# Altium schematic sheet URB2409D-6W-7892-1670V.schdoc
size 277 x 190 mm; Device: default297x210; Symbol: default297x210; Name: default297x210; Date: 2025.06.10; Rev: V1.1; Size: "A4"; Id: /; File: URB2409D-6W-7892-1670V; Sheet: /; @Page No: 1; @Page Count: 1; @Schematic Name: URB2409D-6W-7892-1670V; @Project Name: 无光耦反激隔离电源-URB2409D-6W-7892-1670V; @Board Name: URB2409D-6W-7892-1670V; @Update Date: 2025-06-10; @Create Time: 15:27:42; @Update Time: 11:03:09; @Page Name: URB2409D-6W-7892-1670V; @Create Date: 2025-06-09
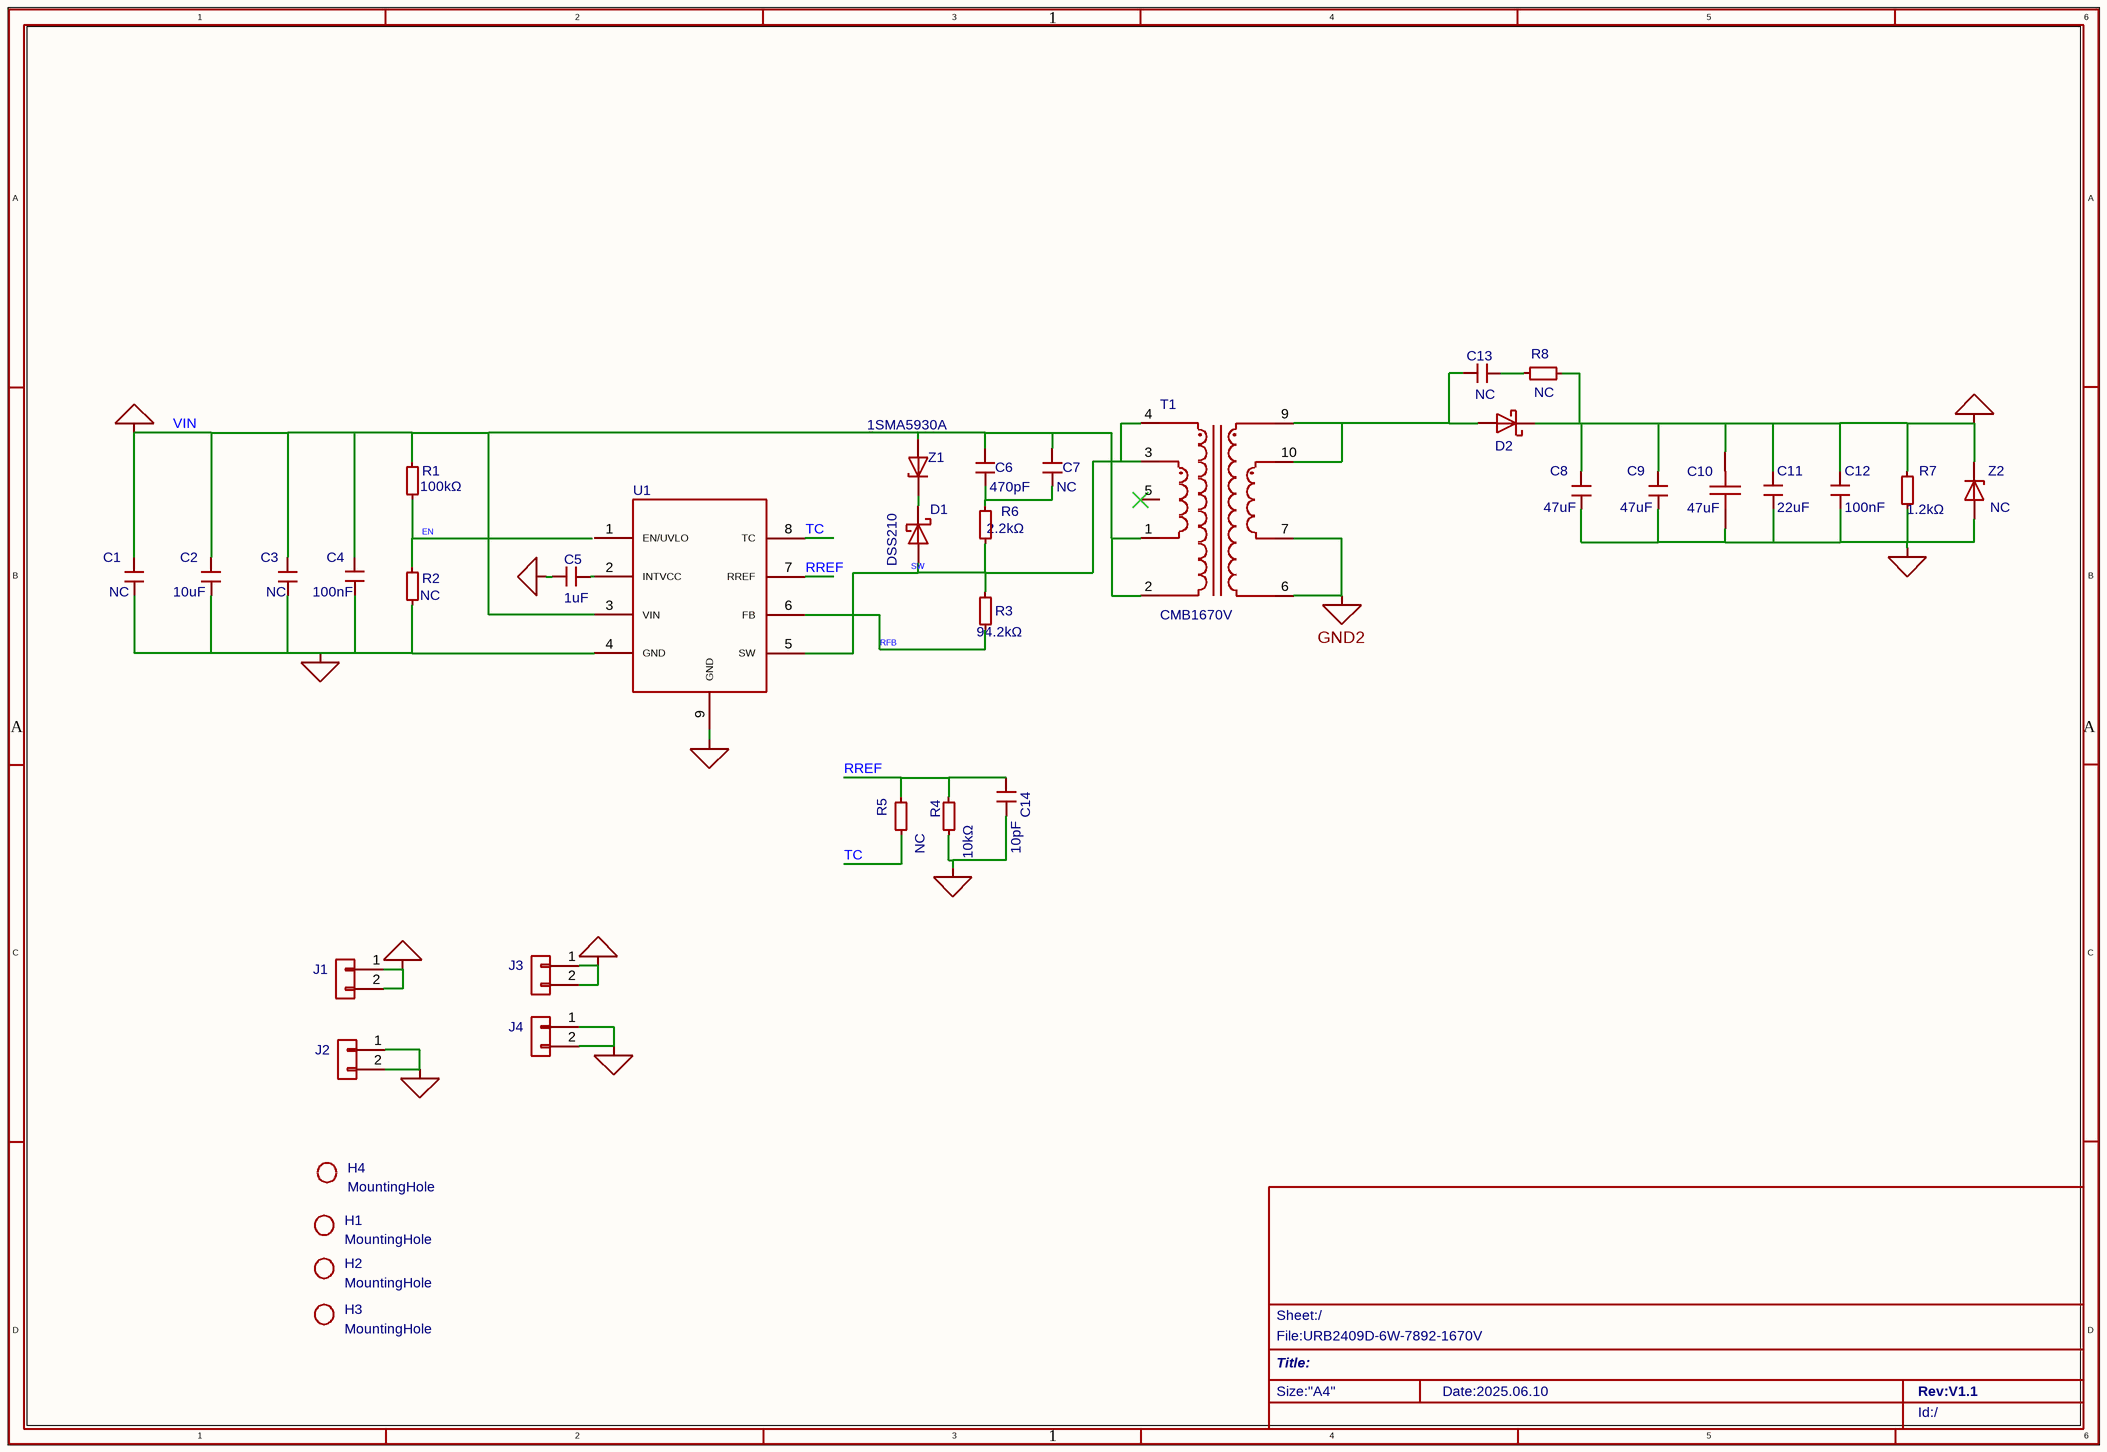
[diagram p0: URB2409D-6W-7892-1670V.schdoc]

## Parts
C1  NC  [C1206]
C2  10uF  [C1206]
C3  NC  [C0805]
C4  100nF  [C0603]
C5  1uF  [C0603]
C6  470pF  [C0603]
C7  NC  [C0603]
C8  47uF  [C1206]
C9  47uF  [C1206]
C10  47uF  [C1206]
C11  22uF  [C0603]
C12  100nF  [C0603]
C13  NC  [C0603]
C14  10pF  [C0603]
D1  DSS210  [SOD-123_L2.8-W1.8-LS3.7-FD]
D2  SSL510B  [SMB_L4.6-W3.5-LS5.3-RD]  (value not drawn)
H1  value MountingHole  [MountingHole:MountingHole_3.2mm_M3_DIN965]  (hidden comment: Mechanical_MountingHole)
H2  value MountingHole  [MountingHole:MountingHole_3.2mm_M3_DIN965]  (hidden comment: Mechanical_MountingHole)
H3  value MountingHole  [MountingHole:MountingHole_3.2mm_M3_DIN965]  (hidden comment: Mechanical_MountingHole)
H4  value MountingHole  [MountingHole:MountingHole_3.2mm_M3_DIN965]  (hidden comment: Mechanical_MountingHole)
J1  Connector_Generic_Conn_01x02  [Connector_PinHeader_2.54mm:PinHeader_1x02_P2.54mm_Vertical]  (value not drawn)
J2  Connector_Generic_Conn_01x02  [Connector_PinHeader_2.54mm:PinHeader_1x02_P2.54mm_Vertical]  (value not drawn)
J3  Connector_Generic_Conn_01x02  [Connector_PinHeader_2.54mm:PinHeader_1x02_P2.54mm_Vertical]  (value not drawn)
J4  Connector_Generic_Conn_01x02  [Connector_PinHeader_2.54mm:PinHeader_1x02_P2.54mm_Vertical]  (value not drawn)
R1  100kΩ  [R0603]
R2  NC  [R0603]
R3  94.2kΩ  [R0603]
R4  10kΩ  [R0603]
R5  value NC  [R0603]  (hidden comment: Device_R_Small)
R6  2.2kΩ  [R0603]
R7  1.2kΩ  [R0603]
R8  value NC  [R0603]  (hidden comment: Device_R_Small)
T1  CMB1670V  [XFMR-SMD_CMB1670V]
U1  (no value)  [ESOP-8_L4.9-W3.9-P1.27-LS6.0-TL-EP3.3]
Z1  1SMA5930A  [SMA_L4.3-W2.6-LS5.2-RD]
Z2  value NC  [DIODE-SMA]  (hidden comment: Diode_BZV55C75)

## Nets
GND1: C1.2 C2.2 C3.2 C4.1 C5.1 C14.1 J2.1(Pin_1) J2.2(Pin_2) R2.2 R4.2 U1.4(GND) U1.9(GND)
GND2: C8.2 C9.2 C10.1 C11.1 C12.1 J4.1(Pin_1) J4.2(Pin_2) R7.1 T1.6 T1.7 Z2.2(A)
VIN: C1.1 C2.1 C3.1 C4.2 C6.1 C7.1 J1.1(Pin_1) J1.2(Pin_2) R1.1 T1.1 T1.2 U1.3(VIN) Z1.2(A)
VOUT: C8.1 C9.1 C10.2 C11.2 C12.2 D2.1(K) J3.1(Pin_1) J3.2(Pin_2) R7.2 R8.1 Z2.1(K)
EN: R1.2 R2.1
RFB: R3.1 U1.6(FB)
RREF: C14.2 R4.1 R5.2 U1.7(RREF)
SW: D1.2(A) R3.2 R6.1 T1.3 T1.4 U1.5(SW)
TC: R5.1 U1.8(TC)
NetC5_2: C5.2 U1.2(INTVCC)
NetC6_2: C6.2 C7.2 R6.2
NetC13_1: C13.1 R8.2
NetC13_2: C13.2 D2.2(A) T1.9 T1.10
NetD1_1: D1.1(K) Z1.1(K)

Not connected (* = marked no-connect by the designer): T1 5*; U1 1(EN/UVLO)

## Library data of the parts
C1 = CC1206KKX5R9BB106: 容值:10uF;精度:±10%;额定电压:50V;材质(温度系数):X5R;; Manufacturer: YAGEO(国巨); Add into BOM: no; Symbol: MY_C; ConvertToPcb: yes; ModelId: e4be705b945545a48e666415e3682bd8; ModelName: C1206_L3.2-W1.6-H1.3; ModelTransform: 125.984,62.992,0,0,0,0,0,0,0; Tolerance: ±10%; Voltage Rated: 50V; Temperature Coefficient: X5R
C2 = CC1206KKX7R8BB106: 容值:10uF;精度:±10%;额定电压:25V;材质(温度系数):X7R;; Manufacturer: YAGEO(国巨); Symbol: MY_C; AddInBom: yes; ModelId: e4be705b945545a48e666415e3682bd8; ModelName: C1206_L3.2-W1.6-H1.3; ModelTransform: 125.984,62.992,0,0,0,0,0,0,0; Tolerance: ±10%; Voltage Rated: 25V; Temperature Coefficient: X7R
C3 = CGA0805X5R476M100MT: 容值:47uF;精度:±20%;额定电压:10V;温度系数:X5R;; Manufacturer: HRE(芯声); Add into BOM: no; Symbol: MY_C; ConvertToPcb: yes; ModelId: 1ba041120af144c991958decab20d241; ModelName: C0805_L2.0-W1.3-H1.3; ModelTransform: 78.74,51.181,0,0,0,0,0,0.0005,0; Tolerance: ±20%; Voltage Rating: 10V; Temperature Coefficient: X5R
C4 C12 = CC0603KRX7R9BB104: 容值:100nF;精度:±10%;额定电压:50V;材质(温度系数):X7R;; Manufacturer: YAGEO(国巨); Symbol: MY_C; AddInBom: yes; ModelId: ac125912035d415993ca9572d50418b1; ModelName: C0603_L1.6-W0.8-H0.8; ModelTransform: 62.992,31.496,0,0,0,0,0,0,0; Tolerance: ±10%; Voltage Rated: 50V; Temperature Coefficient: X7R
C5 = CC0603KRX7R9BB105: 容值:1uF;精度:±10%;额定电压:50V;材质(温度系数):X7R;; Manufacturer: YAGEO(国巨); Symbol: MY_C; AddInBom: yes; ModelId: ac125912035d415993ca9572d50418b1; ModelName: C0603_L1.6-W0.8-H0.8; ModelTransform: 62.992,31.496,0,0,0,0,0,0,0; Tolerance: ±10%; Voltage Rated: 50V; Temperature Coefficient: X7R
C6 = CC0603KRX7R9BB471: 容值:470pF;精度:±10%;额定电压:50V;材质(温度系数):X7R;; Manufacturer: YAGEO(国巨); Symbol: My_library_C; AddInBom: yes; ModelId: ac125912035d415993ca9572d50418b1; ModelName: C0603_L1.6-W0.8-H0.8; ModelTransform: 62.992,31.496,0,0,0,0,0,0,0; Tolerance: ±10%; Voltage Rated: 50V; Temperature Coefficient: X7R
C7 = CC0603KRX7R9BB471: 容值:470pF;精度:±10%;额定电压:50V;材质(温度系数):X7R;; Manufacturer: YAGEO(国巨); Add into BOM: no; Symbol: My_library_C; ConvertToPcb: yes; ModelId: ac125912035d415993ca9572d50418b1; ModelName: C0603_L1.6-W0.8-H0.8; ModelTransform: 62.992,31.496,0,0,0,0,0,0,0; Tolerance: ±10%; Voltage Rated: 50V; Temperature Coefficient: X7R
C8 C9 = C3216X5R1E476MTJ00E: 容值:47uF;精度:±20%;额定电压:25V;温度系数:X5R;; Manufacturer: TDK; Symbol: MY_C; AddInBom: yes; ModelId: e4be705b945545a48e666415e3682bd8; ModelName: C1206_L3.2-W1.6-H1.3; ModelTransform: 125.984,62.992,0,0,0,0,0,0,0; Tolerance: ±20%; Voltage Rating: 25V; Temperature Coefficient: X5R
C10 = C3216X5R1E476MTJ00E: 容值:47uF;精度:±20%;额定电压:25V;温度系数:X5R;; Manufacturer: TDK; Symbol: 1206X226M250NT; AddInBom: yes; ModelId: e4be705b945545a48e666415e3682bd8; ModelName: C1206_L3.2-W1.6-H1.3; ModelTransform: 125.984,62.992,0,0,0,0,0,0,0; Tolerance: ±20%; Voltage Rating: 25V; Temperature Coefficient: X5R
C11 = CL21A226MAQNNNE: 容值:22uF;精度:±20%;额定电压:25V;温度系数:X5R;; Manufacturer: SAMSUNG(三星); 3D Model: 1ba041120af144c991958decab20d241; Symbol: MY_C; AddInBom: yes; ModelName: C0805_L2.0-W1.3-H1.3; ModelTransform: 78.74,51.181,0,0,0,0,0,0.0005,0; Tolerance: ±20%; Voltage Rating: 25V; Temperature Coefficient: X5R
C13 = CGA0603X7R104K500JT: 容值:100nF;精度:±10%;额定电压:50V;温度系数:X7R;; Manufacturer: HRE(芯声); Add into BOM: no; Symbol: My_library_C; ConvertToPcb: yes; ModelId: ac125912035d415993ca9572d50418b1; ModelName: C0603_L1.6-W0.8-H0.8; ModelTransform: 62.992,31.496,0,0,0,0,0,0,0; Value: 100nF; Tolerance: ±10%; Voltage Rating: 50V; Temperature Coefficient: X7R
C14 = CC0603JRNPO9BN100: 容值:10pF;精度:±5%;额定电压:50V;材质(温度系数):NP0;; Manufacturer: YAGEO(国巨); Symbol: My_library_C; AddInBom: yes; ModelId: ac125912035d415993ca9572d50418b1; ModelName: C0603_L1.6-W0.8-H0.8; ModelTransform: 62.992,31.496,0,0,0,0,0,0,0; Tolerance: ±5%; Voltage Rated: 50V; Temperature Coefficient: NP0
D1 = DSS210: 二极管配置:独立式;正向压降(Vf):850mV@2A;直流反向耐压(Vr):100V;整流电流:2A;; Manufacturer: CJ(江苏长电/长晶); Symbol: My library_DSS210; AddInBom: yes; ModelId: 125b22121bda4d3999c0a2016797619b; ModelName: SOD-123_L2.8-W1.8-H1.4-LS3.7; ModelTransform: 145.669,70.866,0,0,0,0,0,0,0; Diode Configuration: 独立式; Reverse Voltage (Vr): 100V; Rectified Current: 2A; Reverse Leakage Current (Ir): 100uA@100V
D2 = SSL510B_C41410776: 二极管配置:独立式;正向压降(Vf):600mV@5.0A;直流反向耐压(Vr):100V;整流电流:5A;; Manufacturer: 宏嘉诚; Symbol: My library_DSS210; AddInBom: yes; ModelId: 0d8fa20d34dd4c86b1864ea8868dcde1; ModelTransform: 208.661,139.764,0,0,0,0,0,0,0; Diode Configuration: 独立式; Voltage - DC Reverse(Vr): 100V; Current - Rectified: 5A; Reverse Leakage Current (Ir): 1mA@100V
H1-H4 = Mechanical_MountingHole: Users: REF**; ki_fp_filters: MountingHole*; AddInBom: yes
J1-J4 = Connector_Generic_Conn_01x02: Generic connector, single row, 01x02, script generated (kicad-library-utils/schlib/autogen/connector/); Users: REF**; ki_fp_filters: Connector*:*_1x??_*; AddInBom: yes
R1 = RC0603FR-07100KL: 电阻类型:厚膜电阻;阻值:100kΩ;精度:±1%;功率:100mW;最大工作电压:75V;温度系数:±100ppm/℃;; Manufacturer: YAGEO(国巨); Symbol: Device_R_Small; AddInBom: yes; ModelId: fc143cca1e79419f9cd78b61e9279f08; ModelTransform: 31.8897,63.7794,0,90,0,0,0,0,0; Tolerance: ±1%; Power(Watts): 100mW; Overload Voltage (Max): 75V
R2 = RC0603FR-0710KL: 电阻类型:厚膜电阻;阻值:10kΩ;精度:±1%;功率:100mW;最大工作电压:75V;温度系数:±100ppm/℃;; Manufacturer: YAGEO(国巨); Add into BOM: no; Symbol: Device_R_Small; ConvertToPcb: yes; ModelId: fc143cca1e79419f9cd78b61e9279f08; ModelTransform: 31.8897,63.7794,0,90,0,0,0,0,0; Tolerance: ±1%; Power(Watts): 100mW; Overload Voltage (Max): 75V
R3 = RT0603BRD0794K2L: 电阻类型:薄膜电阻;阻值:94.2kΩ;精度:±0.1%;功率:100mW;温度系数:±25ppm/℃;; Manufacturer: YAGEO(国巨); Symbol: Device_R_Small; AddInBom: yes; ModelId: fc143cca1e79419f9cd78b61e9279f08; ModelTransform: 31.8897,63.7794,0,90,0,0,0,0,0; Tolerance: ±0.1%; Power(Watts): 100mW
R4 = RC0603FR-0710KL: 电阻类型:厚膜电阻;阻值:10kΩ;精度:±1%;功率:100mW;最大工作电压:75V;温度系数:±100ppm/℃;; Manufacturer: YAGEO(国巨); Symbol: Device_R_Small; AddInBom: yes; ModelId: fc143cca1e79419f9cd78b61e9279f08; ModelTransform: 31.8897,63.7794,0,90,0,0,0,0,0; Tolerance: ±1%; Power(Watts): 100mW; Overload Voltage (Max): 75V
R5 R8 = Device_R_Small: Resistor, small symbol; Add into BOM: no; Origin Footprint: MYLibrary:R0603; Users: REF**; ki_fp_filters: R_*; ConvertToPcb: yes
R6 = RC1206FR-072K2L: 电阻类型:厚膜电阻;阻值:2.2kΩ;精度:±1%;功率:250mW;工作电压:200V;温度系数:±100ppm/℃;; Manufacturer: YAGEO(国巨); 3D Model: 89a1f13db2384da588040e0b3c55bf660819f05c4eef4c71ace90d822a990e87; Symbol: Device_R_Small; Add into BOM: yes; Tolerance: ±1%; ModelName: R1206_L3.2-W1.6-H0.6; ModelTransform: 125.984,62.992,0,0,0,0,0,0,0; Power(Watts): 250mW; Voltage-Supply(Max): 200V
R7 = RC0603FR-071K2L: 电阻类型:厚膜电阻;阻值:1.2kΩ;精度:±1%;功率:100mW;工作电压:75V;温度系数:±100ppm/℃;; Manufacturer: YAGEO(国巨); Symbol: Device_R_Small; Add into BOM: yes; ModelId: fc143cca1e79419f9cd78b61e9279f080819f05c4eef4c71ace90d822a990e87; ModelTransform: 31.8897,63.7794,0,90,0,0,0,0,0; Tolerance: ±1%; Power(Watts): 100mW; Voltage-Supply(Max): 75V
T1 = CMB1670V: Manufacturer: coileasy(线易); AddInBom: yes
U1 = CMP7892: AddInBom: yes; ModelId: f021853bf58e4dc7a473d26afc5d80ba0819f05c4eef4c71ace90d822a990e87; ModelName: ESOP-8_L4.9-W3.9-P1.27-LS6.0-BR-EP3.3; ModelTransform: 192.91300375461577,236.21999999999997,61.02350046932697,0,0,0,0,0,0
Z1 = 1SMA5930A: 二极管配置:独立式;稳压值(标称值):16V;稳压值(范围):14.4V~17.6V;耗散功率(Pd):1.5W;; Manufacturer: LGE(鲁光); Symbol: Diode_BZV55C75; AddInBom: yes; ModelId: e3551acb3c5a4975a5e9d36087fe1fa2; ModelTransform: 185.039,102.362,0,0,0,0,0,0,0; Diode Configuration: 独立式; Zener Voltage(Nom): 16V; Reverse Leakage Current (Ir): 1uA@12.2V; Pd - Power Dissipation: 1.5W; Impedance(Zzt): 10Ω; Impedance(Zzk): 600Ω; Operating Junction Temperature Range: -55℃~+150℃
Z2 = Diode_BZV55C75: Origin Footprint: Diode_SMD:D_SMA; Users: REF**; ki_fp_filters: D*MiniMELF*; AddInBom: yes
